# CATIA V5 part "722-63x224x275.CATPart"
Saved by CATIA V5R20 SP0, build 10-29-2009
Part number: 722-63x224x275
Definition: NONE
Nomenclature: 722-63x224x275
Source: Unknown
Description: 722-63x224x275
Bounding box of the stored display mesh (mm): x -31.5 to 31.5, y -31.5 to 31.5, z -206 to 69
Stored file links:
  C:\Users\Utente\Desktop\IO LAVORO\3D X SITO CF\X SITO\722\722-63x224x275.CATPart
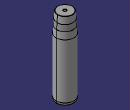
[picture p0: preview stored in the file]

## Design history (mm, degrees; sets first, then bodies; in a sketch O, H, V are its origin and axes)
Body1 "722-63x224x275" (main body)
  Solid1: solid without history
